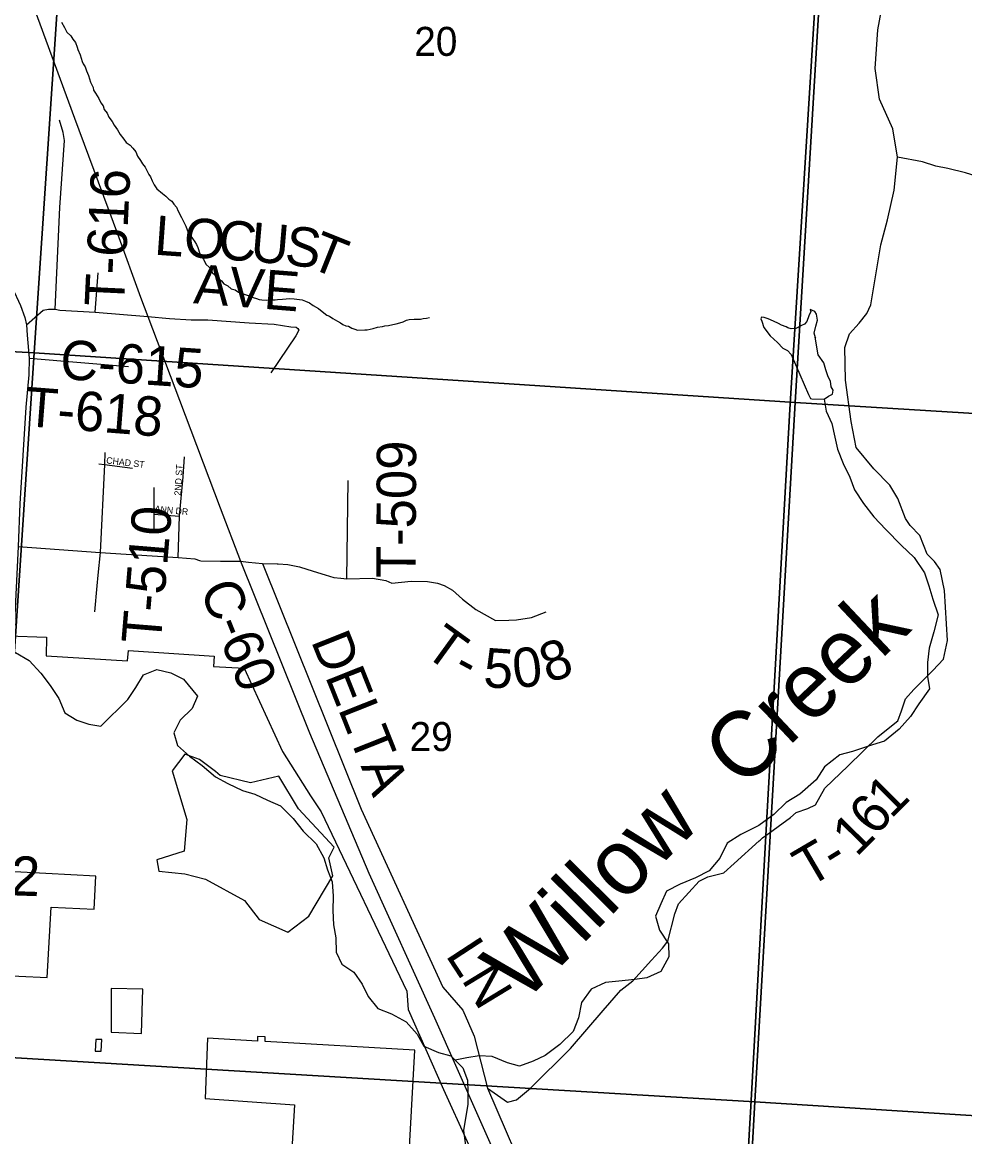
# Model space of a CAD drawing. Extents: x 0 to 34, y 0 to 22.
# Drawn here: x 3.579 to 4.939, y 16.966 to 18.575 of the extents above; entities that cross this region are included whole.
import ezdxf

# ---------------------------------------------------------------- set-up
doc = ezdxf.new("R2010")
doc.units = 0
for name, color, linetype in [('GM_X_Corporation', 7, 'Continuous'), ('GM_X_County_Road', 7, 'Continuous'), ('GM_X_County_Road_Text', 7, 'Continuous'), ('GM_X_Minor_Lake', 7, 'Continuous'), ('GM_X_Minor_River', 7, 'Continuous'), ('GM_X_Minor_River_Text', 7, 'Continuous'), ('GM_X_Section', 7, 'Continuous'), ('GM_X_Section_Text', 7, 'Continuous'), ('GM_X_Township', 7, 'Continuous'), ('GM_X_Township_Road', 7, 'Continuous'), ('GM_X_Township_Road_Text', 7, 'Continuous'), ('GM_X_Township_Subdivision', 7, 'Continuous'), ('GM_X_Township_Subdivision_Text', 7, 'Continuous'), ('GM_X_US_Route', 7, 'Continuous')]:
    doc.layers.add(name, color=color, linetype=linetype)

msp = doc.modelspace()

# ---------------------------------------------------------------- linework, layer by layer
at = {"layer": 'GM_X_Corporation'}
for points in [[(3.5585, 17.6895), (3.6139, 17.6873), (3.6134, 17.6604), (3.7309, 17.6531), (3.7321, 17.6682), (3.8558, 17.6598), (3.8547, 17.6453), (3.8989, 17.6425), (3.9543, 17.5224), (3.9948, 17.4586), (4.0103, 17.4354), (4.1339, 17.1765), (4.1355, 17.1502), (4.1867, 17.0345), (4.3233, 16.7343)], [(3.5324, 17.2003), (3.6148, 17.1961), (3.6203, 17.298), (3.6824, 17.2949), (3.685, 17.3423), (3.5404, 17.35)]]:
    msp.add_lwpolyline(points, dxfattribs=at)
for points in [[(3.8134, 17.5188), (3.7951, 17.4947), (3.8163, 17.4241), (3.8125, 17.3787), (3.7729, 17.3662), (3.7758, 17.3497), (3.8134, 17.3459), (3.8434, 17.3382), (3.8994, 17.3072), (3.9206, 17.2802), (3.9621, 17.2618), (3.9921, 17.285), (4.0268, 17.343), (4.021, 17.3691), (4.0288, 17.3845), (3.9776, 17.4396), (3.9488, 17.487), (3.9081, 17.4773), (3.8646, 17.4879), (3.8578, 17.4937), (3.8347, 17.5111)], [(3.707, 17.1803), (3.707, 17.1174), (3.7511, 17.1152), (3.7526, 17.1796)], [(3.6841, 17.09), (3.6927, 17.09), (3.6934, 17.1068), (3.6848, 17.1068)], [(3.8462, 17.1086), (3.8428, 17.0214), (3.9716, 17.0124), (3.9612, 16.8357), (3.8995, 16.8391), (3.8931, 16.7208), (4.1239, 16.7058), (4.1451, 17.0913), (3.9294, 17.1039), (3.9291, 17.1108), (3.9182, 17.111), (3.9181, 17.1042)]]:
    msp.add_lwpolyline(points, close=True, dxfattribs=at)
at = {"layer": 'GM_X_County_Road'}
for points in [[(3.3918, 18.6508), (3.426, 18.5298), (3.4461, 18.4621), (3.4569, 18.4206), (3.4795, 18.3709), (3.5157, 18.2958), (3.5763, 18.1661), (3.5823, 18.149), (3.5848, 18.1383), (3.5861, 18.1234), (3.5887, 18.09), (3.5881, 18.0662), (3.584, 18.0194), (3.5753, 17.8801), (3.573, 17.8181), (3.5673, 17.6994)], [(3.5848, 18.1383), (3.6091, 18.1592), (3.6167, 18.161), (3.6264, 18.1608), (3.6332, 18.1592), (3.684, 18.1566), (3.7599, 18.1503)], [(3.9254, 17.7939), (4.0679, 17.4392), (4.1855, 17.1823), (4.2145, 17.1491), (4.2307, 17.1117), (4.2501, 17.0363)], [(4.2501, 17.0363), (4.3162, 16.8836), (4.343, 16.8193), (4.4087, 16.6894)]]:
    msp.add_lwpolyline(points, dxfattribs=at)
at = {"layer": 'GM_X_Minor_Lake'}
for points in [[(4.7233, 18.1193), (4.7214, 18.1261), (4.7237, 18.1363), (4.7263, 18.1451), (4.7248, 18.1538), (4.7222, 18.1576), (4.7157, 18.1603), (4.7165, 18.1576), (4.7138, 18.1512), (4.7108, 18.1432), (4.7074, 18.1394), (4.7032, 18.1371), (4.6949, 18.133), (4.6881, 18.1326), (4.6832, 18.1337), (4.6809, 18.1353), (4.6745, 18.1379), (4.67, 18.1402), (4.6628, 18.1433), (4.6548, 18.1471), (4.6492, 18.149), (4.6454, 18.1494), (4.6446, 18.1467), (4.6458, 18.1437), (4.6488, 18.1345), (4.6579, 18.1224), (4.6684, 18.1129), (4.6764, 18.1045), (4.6828, 18.1011), (4.6881, 18.0954), (4.713, 18.0377), (4.716, 18.032), (4.7179, 18.0316), (4.7356, 18.0309)], [(4.7356, 18.0309), (4.7421, 18.0353), (4.7478, 18.0384), (4.7489, 18.0441), (4.7459, 18.0486), (4.7452, 18.057), (4.7418, 18.0634), (4.7384, 18.0733), (4.7353, 18.0832), (4.7274, 18.095), (4.7229, 18.1204), (4.7233, 18.1193)]]:
    msp.add_lwpolyline(points, dxfattribs=at)
at = {"layer": 'GM_X_Minor_River'}
for points in [[(3.6354, 18.5753), (3.6398, 18.5676), (3.6431, 18.5607), (3.6491, 18.5553), (3.6516, 18.5503), (3.6557, 18.5457), (3.6579, 18.5392), (3.659, 18.5354), (3.6626, 18.5277), (3.6651, 18.5185), (3.6669, 18.5151), (3.6695, 18.5105), (3.6713, 18.5048), (3.6746, 18.4982), (3.6771, 18.4887), (3.6811, 18.4807), (3.6818, 18.4769), (3.6847, 18.4726), (3.6895, 18.4649), (3.6921, 18.4588), (3.6954, 18.4542), (3.6972, 18.4492), (3.7013, 18.4435), (3.7038, 18.4381), (3.7086, 18.4319), (3.7112, 18.4262), (3.7164, 18.4196), (3.7201, 18.4127), (3.7256, 18.4062), (3.7289, 18.4016), (3.7346, 18.3973), (3.7383, 18.3931), (3.7427, 18.388), (3.7449, 18.3819), (3.7493, 18.3754), (3.7523, 18.3704), (3.756, 18.3658), (3.7582, 18.3619), (3.7615, 18.3554), (3.7637, 18.352), (3.7662, 18.3462), (3.7692, 18.3405), (3.7728, 18.3347), (3.7811, 18.3277), (3.7859, 18.3238), (3.7904, 18.3196), (3.7945, 18.3165), (3.7975, 18.3126), (3.8015, 18.308), (3.8037, 18.3023), (3.8085, 18.2931), (3.8111, 18.2885), (3.8147, 18.2804), (3.818, 18.2716), (3.8246, 18.2628), (3.8279, 18.2578), (3.8301, 18.2543), (3.8323, 18.2497)], [(3.8323, 18.2497), (3.8348, 18.2409), (3.8404, 18.2332), (3.8437, 18.226), (3.8489, 18.2209), (3.8533, 18.2132), (3.8585, 18.209), (3.8626, 18.2047), (3.8663, 18.2016), (3.8697, 18.1974), (3.8753, 18.1946), (3.8802, 18.1904), (3.8858, 18.1887), (3.8907, 18.1856), (3.8975, 18.1828), (3.9031, 18.1812), (3.9118, 18.1777), (3.917, 18.176), (3.9208, 18.1748), (3.9246, 18.1744), (3.931, 18.1739), (3.9359, 18.1742), (3.9393, 18.1741), (3.9435, 18.1745), (3.9469, 18.1748), (3.9541, 18.1754), (3.9648, 18.176), (3.9712, 18.1759), (3.975, 18.1754), (3.9825, 18.1742), (3.9874, 18.1722), (3.9931, 18.1702), (3.9987, 18.1663), (4.0062, 18.1616), (4.0114, 18.1573), (4.0181, 18.1523), (4.0223, 18.1507), (4.0271, 18.1472), (4.0335, 18.1436), (4.038, 18.1409), (4.0414, 18.1389), (4.0459, 18.137), (4.0493, 18.1362), (4.0542, 18.1334), (4.0587, 18.1322), (4.0624, 18.1306), (4.073, 18.1308), (4.0765, 18.1311), (4.0852, 18.1329), (4.0913, 18.1347), (4.0985, 18.1357), (4.1019, 18.1368), (4.1073, 18.1374), (4.1133, 18.1385), (4.1183, 18.1399), (4.1236, 18.141), (4.1286, 18.1428), (4.1331, 18.145), (4.1369, 18.1457), (4.1445, 18.1463), (4.1479, 18.1462), (4.1532, 18.1465), (4.1574, 18.1472), (4.162, 18.1479), (4.1662, 18.149)], [(4.7356, 18.0309), (4.7385, 18.0134), (4.7468, 17.9959), (4.7513, 17.9761), (4.755, 17.9587), (4.7632, 17.9381), (4.773, 17.9183), (4.7797, 17.9), (4.7925, 17.8802), (4.8076, 17.8612), (4.8249, 17.8429), (4.8468, 17.82), (4.8657, 17.8025), (4.8807, 17.7804), (4.8867, 17.7613), (4.8927, 17.7423), (4.9002, 17.7195), (4.894, 17.6952), (4.8871, 17.6716), (4.8847, 17.6511), (4.8847, 17.6306), (4.8876, 17.6131), (4.8724, 17.5911), (4.8602, 17.5729), (4.8442, 17.5547), (4.8229, 17.5373), (4.8055, 17.5321), (4.7767, 17.5223), (4.7585, 17.5178), (4.7364, 17.5004), (4.7242, 17.4814), (4.7007, 17.461), (4.6809, 17.4489), (4.6634, 17.4315), (4.6414, 17.4156), (4.6156, 17.4027), (4.5959, 17.3899), (4.5852, 17.3686), (4.57, 17.3504), (4.5502, 17.3399), (4.5282, 17.3308), (4.5085, 17.321), (4.5001, 17.3028), (4.4924, 17.2846), (4.4984, 17.2648), (4.5112, 17.245), (4.5119, 17.2259), (4.5004, 17.2047), (4.48, 17.1956), (4.4625, 17.1934), (4.4398, 17.1912), (4.4201, 17.189), (4.3996, 17.1792), (4.3859, 17.1602), (4.3813, 17.1382), (4.3736, 17.1185), (4.3546, 17.0995), (4.3333, 17.0836), (4.3159, 17.0753), (4.2962, 17.0685), (4.2788, 17.0732), (4.2568, 17.0824), (4.2379, 17.0832), (4.2205, 17.0802), (4.2034, 17.0769)], [(3.5692, 17.6651), (3.5889, 17.6536), (3.6055, 17.6353), (3.619, 17.6178), (3.6318, 17.5987), (3.6401, 17.5782), (3.6574, 17.5675), (3.6748, 17.5621), (3.6922, 17.559), (3.731, 17.5976), (3.7425, 17.615), (3.7539, 17.6332), (3.7729, 17.6408), (3.7933, 17.6361), (3.8114, 17.627), (3.8318, 17.6025), (3.8241, 17.5843), (3.8066, 17.5677), (3.7975, 17.5494), (3.8027, 17.5312), (3.8201, 17.5159), (3.8382, 17.5021), (3.8578, 17.4861), (3.8752, 17.4762), (3.8964, 17.4662), (3.9145, 17.4608), (3.9327, 17.4524), (3.9516, 17.4439), (3.9697, 17.4256), (3.984, 17.4073), (4.0028, 17.389), (4.0141, 17.3692), (4.0194, 17.3517), (4.0261, 17.3341), (4.0275, 17.3136)], [(4.0275, 17.3136), (4.0267, 17.2931), (4.0281, 17.2725), (4.0311, 17.2535), (4.0317, 17.233), (4.04, 17.2155), (4.0574, 17.204), (4.0694, 17.1865), (4.0777, 17.1689), (4.092, 17.1514), (4.1117, 17.1437), (4.1328, 17.1322), (4.1487, 17.1147), (4.1584, 17.0972), (4.1796, 17.088), (4.197, 17.0833), (4.2144, 17.0658), (4.2211, 17.0483), (4.2218, 17.0308), (4.2217, 17.0133), (4.2155, 16.9753), (4.2192, 16.9464)]]:
    msp.add_lwpolyline(points, dxfattribs=at)
at = {"layer": 'GM_X_Section'}
for points in [[(3.6625, 19.0898), (3.5959, 18.098), (3.0935, 18.1256)], [(3.0935, 18.1256), (3.5959, 18.098), (3.5285, 17.0826)]]:
    msp.add_lwpolyline(points, dxfattribs=at)
for points in [[(3.6625, 19.0898), (4.754, 19.0266), (4.6942, 18.026), (3.5959, 18.098)], [(4.754, 19.0266), (5.8561, 18.9573), (5.7907, 17.959), (4.6942, 18.026)], [(4.6942, 18.026), (4.636, 17.0167), (3.5285, 17.0826), (3.5959, 18.098)], [(5.7907, 17.959), (5.7237, 16.9481), (4.636, 17.0167), (4.6942, 18.026)], [(3.5285, 17.0826), (4.636, 17.0167), (4.5788, 15.9866), (3.6453, 16.0334), (3.634, 16.0986), (3.6211, 16.1217), (3.6094, 16.1463), (3.6041, 16.1573), (3.595, 16.1759), (3.5844, 16.1967), (3.5753, 16.2123), (3.5678, 16.224), (3.559, 16.2373), (3.5496, 16.2517), (3.5405, 16.2699), (3.5348, 16.2794), (3.5261, 16.2919), (3.4765, 16.3344)], [(4.636, 17.0167), (5.7237, 16.9481), (5.6567, 15.9275), (4.5788, 15.9866)]]:
    msp.add_lwpolyline(points, close=True, dxfattribs=at)
at = {"layer": 'GM_X_Township'}
for points in [[(4.7488, 19.0228), (4.6863, 18.0158), (4.6519, 17.4013), (4.6299, 17.0103), (4.5943, 16.4014)], [(4.5943, 16.4014), (4.6299, 17.0103), (4.6519, 17.4013), (4.6863, 18.0158), (4.7488, 19.0228)]]:
    msp.add_lwpolyline(points, dxfattribs=at)
at = {"layer": 'GM_X_Township_Road'}
for points in [[(4.8416, 18.3803), (4.8347, 18.421), (4.8158, 18.4639), (4.8094, 18.5083), (4.8135, 18.5638), (4.8181, 18.59), (4.8344, 18.6382), (4.8439, 18.697), (4.8537, 18.7722), (4.8636, 18.8398), (4.8772, 18.8865), (4.8905, 18.927), (4.8996, 18.9558), (4.8951, 19.0015), (4.8908, 19.0136), (4.8873, 19.0236), (4.8872, 19.0239)], [(3.6264, 18.1608), (3.6328, 18.3077), (3.6397, 18.4043), (3.6378, 18.4158), (3.6324, 18.4336)], [(4.6421, 17.3933), (4.6435, 17.3946), (4.6471, 17.3978), (4.6519, 17.4013), (4.6873, 17.4271), (4.6956, 17.4343), (4.7123, 17.44), (4.7233, 17.4453), (4.7369, 17.4693), (4.7703, 17.5019), (4.8131, 17.5437), (4.8331, 17.5593), (4.8419, 17.5669), (4.8472, 17.581), (4.8532, 17.5984), (4.8653, 17.6121), (4.8926, 17.6391), (4.9081, 17.6558), (4.9138, 17.6828), (4.9093, 17.755), (4.9032, 17.785), (4.8949, 17.7968), (4.8843, 17.8074), (4.8741, 17.834), (4.8601, 17.8485), (4.8532, 17.8588), (4.8423, 17.8876), (4.8305, 17.907), (4.8074, 17.9306), (4.782, 17.9614), (4.7748, 17.9986), (4.7665, 18.0586), (4.7658, 18.1054), (4.7726, 18.1251), (4.7862, 18.1407), (4.7976, 18.1544), (4.8033, 18.1673), (4.8177, 18.2535), (4.8272, 18.29), (4.837, 18.3325), (4.8416, 18.3803)], [(5.2666, 18.233), (5.2525, 18.2612), (5.2288, 18.2944), (5.2051, 18.3181), (5.1798, 18.3308), (5.1624, 18.3292), (5.1498, 18.3292), (5.1339, 18.3339), (5.1197, 18.3418), (5.0976, 18.3529), (5.0739, 18.3576), (5.0518, 18.3576), (5.0265, 18.3545), (5.0028, 18.3513), (4.9601, 18.3513), (4.9396, 18.3576), (4.9143, 18.3639), (4.8969, 18.3671), (4.8779, 18.3734), (4.8416, 18.3803)], [(3.684, 18.1566), (3.6883, 18.2132)], [(3.7599, 18.1503), (3.7915, 18.1475), (3.8225, 18.1456), (3.8465, 18.1453), (3.9064, 18.1411), (3.9422, 18.139), (3.9662, 18.1355), (3.9742, 18.1348), (3.9763, 18.1331), (3.9777, 18.1307), (3.9735, 18.1223), (3.9377, 18.069)], [(3.5887, 18.09), (3.7319, 18.0782)], [(3.6982, 17.9539), (3.6974, 17.9366), (3.6911, 17.8095), (3.6877, 17.7769)], [(4.0472, 17.7715), (4.0489, 17.9134)], [(3.573, 17.8181), (3.6911, 17.8095), (3.8039, 17.8025), (3.8278, 17.8004), (3.8347, 17.7981)], [(3.8347, 17.7981), (3.8364, 17.7975), (3.865, 17.7973)], [(3.865, 17.7973), (3.8936, 17.7971), (3.9053, 17.7959)], [(3.9053, 17.7959), (3.9254, 17.7939), (3.9465, 17.7934)], [(3.9465, 17.7934), (3.9482, 17.7933), (3.9622, 17.7925), (3.9787, 17.7888), (3.9984, 17.7825), (4.0161, 17.7774), (4.0283, 17.7736), (4.0385, 17.7725)], [(3.6877, 17.7769), (3.6862, 17.7617), (3.683, 17.7239)], [(4.0385, 17.7725), (4.0472, 17.7715), (4.0843, 17.7724), (4.1032, 17.769), (4.1119, 17.7655), (4.1398, 17.7683), (4.1636, 17.7676), (4.1778, 17.7652), (4.1874, 17.7621), (4.1995, 17.7555), (4.214, 17.7421), (4.2333, 17.7272), (4.2616, 17.7117), (4.281, 17.712), (4.292, 17.7124), (4.3134, 17.7158), (4.3348, 17.7238)], [(4.2501, 17.0363), (4.2789, 17.0163), (4.2918, 17.0197), (4.3119, 17.0364), (4.3698, 17.0938), (4.4172, 17.1485), (4.4426, 17.1782), (4.46, 17.1915), (4.4869, 17.2211), (4.5024, 17.2386), (4.5104, 17.2489), (4.5202, 17.288), (4.5259, 17.3028), (4.5555, 17.3351), (4.568, 17.3416), (4.5911, 17.3473), (4.6062, 17.3606), (4.6421, 17.3933)]]:
    msp.add_lwpolyline(points, dxfattribs=at)
at = {"layer": 'GM_X_Township_Subdivision'}
for points in [[(3.6891, 17.9377), (3.6974, 17.9366), (3.7377, 17.9313)], [(3.8109, 17.9188), (3.811, 17.9194), (3.8128, 17.9479)], [(3.8039, 17.8025), (3.8058, 17.8619), (3.8109, 17.9188)], [(3.7688, 17.9034), (3.7688, 17.8652), (3.7688, 17.8443)], [(3.7688, 17.8652), (3.8058, 17.8619)]]:
    msp.add_lwpolyline(points, dxfattribs=at)
at = {"layer": 'GM_X_US_Route'}
for points in [[(3.4004, 19.0243), (3.4386, 18.9612), (3.4619, 18.9191), (3.484, 18.876), (3.4957, 18.851), (3.5126, 18.8094), (3.5341, 18.7561), (3.5713, 18.6622), (3.654, 18.4363), (3.7163, 18.2698), (3.7496, 18.1784)], [(3.7496, 18.1784), (3.7599, 18.1503), (3.8059, 18.0295), (3.8644, 17.8742), (3.8936, 17.7971), (3.9933, 17.5496), (4.0789, 17.3466), (4.1735, 17.1378), (4.2703, 16.9203), (4.3388, 16.7642), (4.3703, 16.6944)]]:
    msp.add_lwpolyline(points, dxfattribs=at)

# ---------------------------------------------------------------- texts
at = {"layer": 'GM_X_County_Road_Text'}
for s, height, rotation, p in [('C-615', 0.05682, 356.1656, (3.6322, 18.0603)), ('C-60', 0.05682, 291.8015, (3.8344, 17.7572)), ('DELTA', 0.05682, 291.685, (3.995, 17.6821)), ('L', 0.0568, 303.1568, (4.1887, 17.2285)), ('N', 0.0568, 301.3202, (4.2117, 17.1933))]:
    msp.add_text(s, height=height, rotation=rotation, dxfattribs=at).set_placement(p)
at = {"layer": 'GM_X_Minor_River_Text'}
for s, height, rotation, p in [('Creek', 0.09474, 43.2807, (4.6177, 17.4663)), ('Willow', 0.09475, 45.243, (4.302, 17.1576))]:
    msp.add_text(s, height=height, rotation=rotation, dxfattribs=at).set_placement(p)
at = {"layer": 'GM_X_Section_Text'}
for s, p in [('20', (4.1444, 18.5264)), ('29', (4.1377, 17.5231))]:
    msp.add_text(s, height=0.04186, rotation=0, dxfattribs=at).set_placement(p)
at = {"layer": 'GM_X_Township_Road_Text'}
for s, height, rotation, p in [('T-616', 0.05682, 87.2565, (3.7254, 18.1638)), ('L', 0.0568, 355.951, (3.7682, 18.2396)), ('O', 0.0568, 355.9508, (3.8106, 18.2366)), ('C', 0.0568, 355.9506, (3.8604, 18.2331)), ('U', 0.0568, 355.2079, (3.9068, 18.2298)), ('S', 0.0568, 352.7483, (3.956, 18.2257)), ('T', 0.0568, 338.228, (3.9903, 18.2218)), ('AVE', 0.05682, 355.4831, (3.825, 18.1695)), ('T-618', 0.05682, 355.5153, (3.5817, 17.9922)), ('T-509', 0.05682, 89.7193, (4.1463, 17.7726)), ('T-510', 0.05682, 85.2833, (3.7785, 17.6764)), ('T', 0.0568, 324.1291, (4.1562, 17.6633)), ('8', 0.0568, 19.4314, (4.3378, 17.6206)), ('5', 0.0568, 355.928, (4.2431, 17.6157)), ('0', 0.0568, 6.5317, (4.2895, 17.6135)), ('-', 0.0568, 331.6167, (4.1975, 17.6341)), ('1', 0.0568, 44.7226, (4.8321, 17.4243)), ('6', 0.0568, 50.8232, (4.811, 17.3984)), ('1', 0.0568, 45.5093, (4.7827, 17.3691)), ('T', 0.0568, 30.3684, (4.7133, 17.3254)), ('T-362', 0.05682, 358.0347, (3.4052, 17.3203)), ('-', 0.0568, 31.626, (4.7511, 17.3476))]:
    msp.add_text(s, height=height, rotation=rotation, dxfattribs=at).set_placement(p)
at = {"layer": 'GM_X_Township_Subdivision_Text'}
for s, rotation, p in [('CHAD ST', 353.2336, (3.6996, 17.9382)), ('2ND ST', 86.3495, (3.8076, 17.8915)), ('ANN DR', 354.6107, (3.7695, 17.8681))]:
    msp.add_text(s, height=0.00947, rotation=rotation, dxfattribs=at).set_placement(p)

doc.saveas('drawing.dxf')
